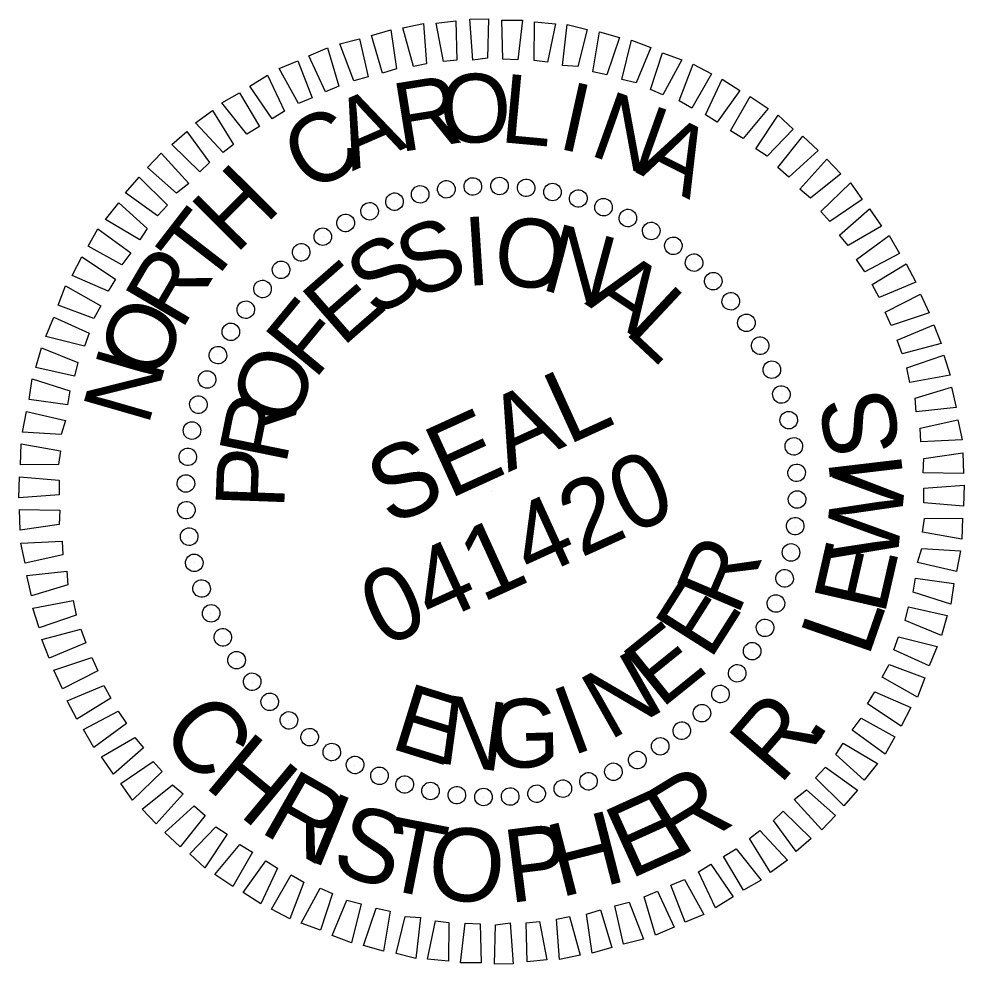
# Model space of a CAD drawing. Extents: x 2245059 to 2247045, y 661437 to 663204.
# Drawn here: x 2246903.7 to 2246981.3, y 663126.9 to 663204.4 of the extents above; entities that cross this region are included whole.
import ezdxf

# ---------------------------------------------------------------- set-up
doc = ezdxf.new("R2010")
doc.units = 0
doc.layers.add('Sheet PE Seal Cell', color=7, linetype='Continuous')

msp = doc.modelspace()

# ---------------------------------------------------------------- linework, layer by layer
at = {"layer": 'Sheet PE Seal Cell'}
for p, q in [((2246940.978, 663190.735), (2246940.978, 663190.735)), ((2246943.171, 663190.745), (2246943.171, 663190.745)), ((2246945.36, 663190.644), (2246945.36, 663190.644)), ((2246936.679, 663190.04), (2246936.679, 663190.04)), ((2246938.777, 663190.501), (2246938.777, 663190.501)), ((2246947.516, 663190.253), (2246947.516, 663190.253)), ((2246934.577, 663189.467), (2246934.577, 663189.467)), ((2246949.669, 663189.75), (2246949.669, 663189.75)), ((2246932.513, 663188.691), (2246932.513, 663188.691)), ((2246951.701, 663189.028), (2246951.701, 663189.028)), ((2246930.532, 663187.734), (2246930.532, 663187.734)), ((2246953.75, 663188.149), (2246953.75, 663188.149)), ((2246955.613, 663187.074), (2246955.613, 663187.074)), ((2246928.7, 663186.569), (2246928.7, 663186.569)), ((2246926.864, 663185.293), (2246926.864, 663185.293)), ((2246957.448, 663185.822), (2246957.448, 663185.822)), ((2246959.166, 663184.462), (2246959.166, 663184.462)), ((2246925.202, 663183.876), (2246925.202, 663183.876)), ((2246960.724, 663182.974), (2246960.724, 663182.974)), ((2246923.714, 663182.319), (2246923.714, 663182.319)), ((2246962.14, 663181.312), (2246962.14, 663181.312)), ((2246922.354, 663180.6), (2246922.354, 663180.6)), ((2246963.417, 663179.476), (2246963.417, 663179.476)), ((2246921.102, 663178.766), (2246921.102, 663178.766)), ((2246964.581, 663177.644), (2246964.581, 663177.644)), ((2246920.028, 663176.903), (2246920.028, 663176.903)), ((2246965.539, 663175.663), (2246965.539, 663175.663)), ((2246919.148, 663174.854), (2246919.148, 663174.854)), ((2246966.315, 663173.599), (2246966.315, 663173.599)), ((2246918.426, 663172.821), (2246918.426, 663172.821)), ((2246966.888, 663171.497), (2246966.888, 663171.497)), ((2246917.923, 663170.669), (2246917.923, 663170.669)), ((2246967.349, 663169.399), (2246967.349, 663169.399)), ((2246917.532, 663168.513), (2246917.532, 663168.513)), ((2246967.583, 663167.198), (2246967.583, 663167.198)), ((2246917.431, 663166.323), (2246917.431, 663166.323)), ((2246942.512, 663165.664), (2246942.512, 663165.664)), ((2246967.593, 663165.005), (2246967.593, 663165.005)), ((2246917.441, 663164.13), (2246917.441, 663164.13)), ((2246967.492, 663162.816), (2246967.492, 663162.816)), ((2246917.675, 663161.929), (2246917.675, 663161.929)), ((2246967.101, 663160.66), (2246967.101, 663160.66)), ((2246918.136, 663159.832), (2246918.136, 663159.832)), ((2246966.598, 663158.507), (2246966.598, 663158.507)), ((2246918.709, 663157.73), (2246918.709, 663157.73)), ((2246965.876, 663156.475), (2246965.876, 663156.475)), ((2246919.485, 663155.666), (2246919.485, 663155.666)), ((2246964.996, 663154.426), (2246964.996, 663154.426)), ((2246920.443, 663153.685), (2246920.443, 663153.685)), ((2246921.607, 663151.853), (2246921.607, 663151.853)), ((2246963.922, 663152.563), (2246963.922, 663152.563)), ((2246962.67, 663150.728), (2246962.67, 663150.728)), ((2246922.883, 663150.016), (2246922.883, 663150.016)), ((2246961.31, 663149.01), (2246961.31, 663149.01)), ((2246924.3, 663148.354), (2246924.3, 663148.354)), ((2246959.822, 663147.453), (2246959.822, 663147.453)), ((2246925.857, 663146.866), (2246925.857, 663146.866)), ((2246958.16, 663146.036), (2246958.16, 663146.036)), ((2246927.576, 663145.506), (2246927.576, 663145.506)), ((2246929.41, 663144.254), (2246929.41, 663144.254)), ((2246956.324, 663144.76), (2246956.324, 663144.76)), ((2246954.492, 663143.595), (2246954.492, 663143.595)), ((2246931.273, 663143.18), (2246931.273, 663143.18)), ((2246952.51, 663142.637), (2246952.51, 663142.637)), ((2246933.323, 663142.301), (2246933.323, 663142.301)), ((2246950.446, 663141.862), (2246950.446, 663141.862)), ((2246935.355, 663141.578), (2246935.355, 663141.578)), ((2246937.507, 663141.076), (2246937.507, 663141.076)), ((2246948.345, 663141.288), (2246948.345, 663141.288)), ((2246939.664, 663140.684), (2246939.664, 663140.684)), ((2246941.853, 663140.583), (2246941.853, 663140.583)), ((2246944.046, 663140.593), (2246944.046, 663140.593)), ((2246946.247, 663140.827), (2246946.247, 663140.827))]:
    msp.add_line(p, q, dxfattribs=at)
for points in [[(2246936.119, 663200.554), (2246935.226, 663203.719), (2246936.939, 663204.06), (2246937.178, 663200.762)], [(2246938.572, 663200.958), (2246937.969, 663204.09), (2246939.587, 663204.278), (2246939.673, 663201.075)], [(2246940.993, 663201.072), (2246940.733, 663204.415), (2246942.256, 663204.45), (2246942.185, 663201.23)], [(2246943.434, 663201.14), (2246943.349, 663204.343), (2246945.049, 663204.349), (2246944.663, 663201.096)], [(2246946.004, 663201.048), (2246946.051, 663204.201), (2246947.768, 663204.049), (2246947.117, 663200.896)], [(2246948.338, 663200.628), (2246948.728, 663203.992), (2246950.347, 663203.576), (2246949.588, 663200.538)], [(2246933.57, 663199.997), (2246932.653, 663203.096), (2246934.258, 663203.553), (2246934.724, 663200.358)], [(2246950.826, 663200.113), (2246951.369, 663203.382), (2246953.008, 663202.921), (2246951.981, 663199.87)], [(2246931.221, 663199.366), (2246930.055, 663202.407), (2246931.681, 663202.818), (2246932.395, 663199.682)], [(2246953.197, 663199.49), (2246953.985, 663202.706), (2246955.574, 663202.112), (2246954.373, 663199.202)], [(2246928.883, 663198.466), (2246927.536, 663201.423), (2246929.058, 663202.062), (2246929.996, 663198.918)], [(2246955.561, 663198.644), (2246956.543, 663201.674), (2246958.133, 663201.08), (2246956.575, 663198.227)], [(2246926.679, 663197.516), (2246925.104, 663200.37), (2246926.626, 663201.009), (2246927.791, 663197.968)], [(2246957.9, 663197.732), (2246959.06, 663200.733), (2246960.575, 663199.94), (2246958.952, 663197.112)], [(2246924.507, 663196.252), (2246922.68, 663198.936), (2246924.144, 663199.823), (2246925.537, 663196.886)], [(2246960.073, 663196.579), (2246961.432, 663199.506), (2246962.898, 663198.581), (2246961.013, 663195.964)], [(2246922.448, 663194.984), (2246920.393, 663197.564), (2246921.832, 663198.385), (2246923.478, 663195.618)], [(2246962.107, 663195.253), (2246963.73, 663198.081), (2246965.217, 663197.11), (2246963.158, 663194.633)], [(2246920.492, 663193.488), (2246918.23, 663195.919), (2246919.632, 663196.943), (2246921.344, 663194.151)], [(2246964.202, 663193.79), (2246966.024, 663196.544), (2246967.258, 663195.403), (2246965.142, 663193.175)], [(2246918.578, 663191.902), (2246916.287, 663194.155), (2246917.511, 663195.207), (2246919.388, 663192.656)], [(2246966.003, 663192.248), (2246968.066, 663194.837), (2246969.321, 663193.65), (2246966.914, 663191.455)], [(2246916.68, 663190.158), (2246914.294, 663192.258), (2246915.411, 663193.426), (2246917.693, 663190.949)], [(2246967.797, 663190.483), (2246970.033, 663192.931), (2246971.176, 663191.748), (2246968.687, 663189.735)], [(2246915.113, 663188.29), (2246912.496, 663190.175), (2246913.616, 663191.454), (2246915.928, 663189.156)], [(2246969.52, 663188.631), (2246971.955, 663191.004), (2246972.912, 663189.627), (2246970.274, 663187.821)], [(2246913.654, 663186.307), (2246910.851, 663187.996), (2246911.93, 663189.367), (2246914.27, 663187.246)], [(2246971.061, 663186.696), (2246973.533, 663188.866), (2246974.511, 663187.444), (2246971.769, 663185.865)], [(2246912.171, 663184.257), (2246909.43, 663185.81), (2246910.219, 663187.214), (2246912.923, 663185.259)], [(2246972.466, 663184.698), (2246975.133, 663186.683), (2246975.974, 663185.198), (2246973.145, 663183.689)], [(2246911.064, 663182.104), (2246908.112, 663183.396), (2246908.905, 663184.912), (2246911.659, 663183.089)], [(2246973.734, 663182.639), (2246976.525, 663184.351), (2246977.321, 663182.845), (2246974.322, 663181.588)], [(2246909.887, 663179.864), (2246906.972, 663180.954), (2246907.567, 663182.543), (2246910.461, 663180.895)], [(2246974.816, 663180.385), (2246977.711, 663181.869), (2246978.416, 663180.322), (2246975.314, 663179.293)], [(2246909.111, 663177.588), (2246905.94, 663178.396), (2246906.601, 663179.96), (2246909.507, 663178.647)], [(2246975.807, 663178.089), (2246978.806, 663179.346), (2246979.399, 663177.803), (2246976.214, 663176.956)], [(2246908.306, 663175.133), (2246905.132, 663175.829), (2246905.594, 663177.468), (2246908.57, 663176.242)], [(2246976.575, 663175.801), (2246979.611, 663176.855), (2246980.134, 663175.225), (2246976.845, 663174.606)], [(2246907.729, 663172.782), (2246904.567, 663173.209), (2246904.83, 663174.923), (2246907.927, 663173.916)], [(2246977.268, 663173.315), (2246980.255, 663174.237), (2246980.641, 663172.545), (2246977.34, 663172.194)], [(2246907.193, 663170.34), (2246904.024, 663170.544), (2246904.353, 663172.233), (2246907.548, 663171.491)], [(2246977.672, 663170.862), (2246980.762, 663171.556), (2246981.128, 663169.909), (2246977.743, 663169.74)], [(2246906.993, 663167.886), (2246903.881, 663167.842), (2246903.921, 663169.563), (2246907.145, 663168.999)], [(2246977.985, 663168.367), (2246981.179, 663168.833), (2246981.23, 663167.153), (2246977.92, 663167.183)], [(2246907.037, 663165.378), (2246903.739, 663165.139), (2246903.779, 663166.861), (2246907.036, 663166.587)], [(2246977.987, 663165.95), (2246981.285, 663166.189), (2246981.245, 663164.468), (2246977.988, 663164.742)], [(2246907.039, 663162.962), (2246903.845, 663162.495), (2246903.794, 663164.175), (2246907.104, 663164.145)], [(2246978.031, 663163.443), (2246981.142, 663163.487), (2246981.103, 663161.765), (2246977.879, 663162.329)], [(2246907.352, 663160.467), (2246904.261, 663159.773), (2246903.896, 663161.42), (2246907.28, 663161.588)], [(2246977.83, 663160.988), (2246981, 663160.785), (2246980.671, 663159.096), (2246977.475, 663159.838)], [(2246907.755, 663158.013), (2246904.769, 663157.092), (2246904.382, 663158.784), (2246907.684, 663159.135)], [(2246977.295, 663158.547), (2246980.456, 663158.119), (2246980.193, 663156.406), (2246977.097, 663157.413)], [(2246908.449, 663155.527), (2246905.413, 663154.473), (2246904.89, 663156.103), (2246908.179, 663156.723)], [(2246976.717, 663156.196), (2246979.892, 663155.499), (2246979.43, 663153.86), (2246976.454, 663155.086)], [(2246909.217, 663153.239), (2246906.218, 663151.983), (2246905.624, 663153.526), (2246908.81, 663154.373)], [(2246975.913, 663153.741), (2246979.083, 663152.933), (2246978.423, 663151.368), (2246975.517, 663152.681)], [(2246910.208, 663150.944), (2246907.312, 663149.46), (2246906.608, 663151.007), (2246909.71, 663152.036)], [(2246975.137, 663151.464), (2246978.051, 663150.375), (2246977.457, 663148.785), (2246974.563, 663150.433)], [(2246911.29, 663148.69), (2246908.498, 663146.978), (2246907.702, 663148.483), (2246910.701, 663149.74)], [(2246973.96, 663149.225), (2246976.911, 663147.932), (2246976.118, 663146.417), (2246973.365, 663148.239)], [(2246912.558, 663146.63), (2246909.891, 663144.645), (2246909.049, 663146.13), (2246911.878, 663147.639)], [(2246972.853, 663147.072), (2246975.594, 663145.518), (2246974.805, 663144.115), (2246972.101, 663146.07)], [(2246913.963, 663144.633), (2246911.49, 663142.462), (2246910.512, 663143.885), (2246913.254, 663145.464)], [(2246971.369, 663145.022), (2246974.172, 663143.332), (2246973.094, 663141.961), (2246970.754, 663144.082)], [(2246915.504, 663142.698), (2246913.069, 663140.324), (2246912.112, 663141.701), (2246914.75, 663143.508)], [(2246969.91, 663143.039), (2246972.527, 663141.154), (2246971.407, 663139.874), (2246969.096, 663142.173)], [(2246917.227, 663140.845), (2246914.991, 663138.398), (2246913.847, 663139.58), (2246916.337, 663141.594)], [(2246968.344, 663141.171), (2246970.729, 663139.071), (2246969.613, 663137.903), (2246967.331, 663140.379)], [(2246919.02, 663139.08), (2246916.958, 663136.492), (2246915.703, 663137.678), (2246918.109, 663139.874)], [(2246966.446, 663139.427), (2246968.737, 663137.174), (2246967.513, 663136.122), (2246965.636, 663138.673)], [(2246920.822, 663137.538), (2246919, 663134.785), (2246917.765, 663135.926), (2246919.882, 663138.154)], [(2246964.532, 663137.84), (2246966.793, 663135.409), (2246965.392, 663134.386), (2246963.68, 663137.177)], [(2246922.917, 663136.075), (2246921.294, 663133.248), (2246919.807, 663134.219), (2246921.866, 663136.695)], [(2246962.576, 663136.345), (2246964.631, 663133.764), (2246963.191, 663132.944), (2246961.546, 663135.71)], [(2246924.95, 663134.749), (2246923.592, 663131.822), (2246922.126, 663132.748), (2246924.01, 663135.365)], [(2246960.516, 663135.076), (2246962.344, 663132.392), (2246960.88, 663131.506), (2246959.486, 663134.442)], [(2246927.124, 663133.597), (2246925.964, 663130.595), (2246924.449, 663131.388), (2246926.072, 663134.216)], [(2246958.345, 663133.812), (2246959.92, 663130.958), (2246958.398, 663130.32), (2246957.232, 663133.36)], [(2246929.463, 663132.684), (2246928.481, 663129.654), (2246926.891, 663130.249), (2246928.448, 663133.101)], [(2246956.14, 663132.863), (2246957.488, 663129.905), (2246955.966, 663129.266), (2246955.028, 663132.41)], [(2246931.826, 663131.838), (2246931.039, 663128.622), (2246929.449, 663129.217), (2246930.651, 663132.127)], [(2246953.803, 663131.962), (2246954.969, 663128.922), (2246953.343, 663128.511), (2246952.628, 663131.647)], [(2246934.198, 663131.216), (2246933.655, 663127.946), (2246932.016, 663128.408), (2246933.043, 663131.459)], [(2246951.453, 663131.331), (2246952.371, 663128.233), (2246950.766, 663127.776), (2246950.299, 663130.97)], [(2246936.685, 663130.701), (2246936.295, 663127.336), (2246934.677, 663127.753), (2246935.436, 663130.791)], [(2246939.02, 663130.281), (2246938.973, 663127.128), (2246937.255, 663127.279), (2246937.906, 663130.433)], [(2246941.589, 663130.188), (2246941.675, 663126.985), (2246939.974, 663126.98), (2246940.36, 663130.232)], [(2246944.031, 663130.257), (2246944.29, 663126.913), (2246942.768, 663126.879), (2246942.839, 663130.098)], [(2246946.451, 663130.371), (2246947.054, 663127.239), (2246945.437, 663127.051), (2246945.351, 663130.254)], [(2246948.905, 663130.774), (2246949.798, 663127.61), (2246948.085, 663127.269), (2246947.846, 663130.566)]]:
    msp.add_lwpolyline(points, close=True, dxfattribs=at)
for centre, major_axis in [((2246940.982, 663190.698), (-0.044, 0.719)), ((2246943.169, 663190.736), (0.019, 0.72)), ((2246936.658, 663190.052), (-0.168, 0.7)), ((2246938.806, 663190.469), (-0.106, 0.712)), ((2246945.352, 663190.583), (0.082, 0.715)), ((2246947.513, 663190.241), (0.144, 0.706)), ((2246934.555, 663189.449), (-0.228, 0.683)), ((2246949.636, 663189.711), (0.205, 0.69)), ((2246932.512, 663188.664), (-0.287, 0.66)), ((2246951.705, 663188.999), (0.264, 0.67)), ((2246930.545, 663187.705), (-0.344, 0.633)), ((2246953.703, 663188.109), (0.321, 0.644)), ((2246955.617, 663187.048), (0.376, 0.614)), ((2246928.67, 663186.579), (-0.397, 0.6)), ((2246926.9, 663185.293), (-0.448, 0.563)), ((2246957.431, 663185.824), (0.428, 0.579)), ((2246959.131, 663184.447), (0.477, 0.539)), ((2246925.249, 663183.857), (-0.496, 0.522)), ((2246960.705, 663182.928), (0.522, 0.496)), ((2246923.729, 663182.283), (-0.539, 0.477)), ((2246962.14, 663181.276), (0.563, 0.448)), ((2246922.352, 663180.583), (-0.579, 0.428)), ((2246963.426, 663179.506), (0.6, 0.397)), ((2246921.128, 663178.769), (-0.614, 0.376)), ((2246964.553, 663177.631), (0.633, 0.344)), ((2246920.067, 663176.856), (-0.644, 0.321)), ((2246965.512, 663175.664), (0.66, 0.287)), ((2246919.177, 663174.857), (-0.67, 0.264)), ((2246966.296, 663173.621), (0.683, 0.228)), ((2246918.465, 663172.788), (-0.69, 0.205)), ((2246966.899, 663171.518), (0.7, 0.168)), ((2246917.936, 663170.665), (-0.706, 0.144)), ((2246967.316, 663169.37), (0.712, 0.106)), ((2246917.593, 663168.504), (-0.715, 0.082)), ((2246967.545, 663167.194), (0.719, 0.044)), ((2246917.44, 663166.322), (-0.72, 0.019)), ((2246967.583, 663165.007), (0.72, -0.019)), ((2246917.479, 663164.134), (-0.719, -0.044)), ((2246967.431, 663162.824), (0.715, -0.082)), ((2246917.707, 663161.958), (-0.712, -0.106)), ((2246967.088, 663160.663), (0.706, -0.144)), ((2246918.125, 663159.81), (-0.7, -0.168)), ((2246966.559, 663158.54), (0.69, -0.205)), ((2246918.728, 663157.707), (-0.683, -0.228)), ((2246965.846, 663156.472), (0.67, -0.264)), ((2246919.512, 663155.664), (-0.66, -0.287)), ((2246964.956, 663154.473), (0.644, -0.321)), ((2246920.471, 663153.698), (-0.633, -0.344)), ((2246963.896, 663152.559), (0.614, -0.376)), ((2246921.597, 663151.822), (-0.6, -0.397)), ((2246962.672, 663150.745), (0.579, -0.428)), ((2246922.883, 663150.052), (-0.563, -0.448)), ((2246961.295, 663149.045), (0.539, -0.477)), ((2246924.319, 663148.401), (-0.522, -0.496)), ((2246959.775, 663147.471), (0.496, -0.522)), ((2246925.893, 663146.881), (-0.477, -0.539)), ((2246958.124, 663146.036), (0.448, -0.563)), ((2246927.593, 663145.504), (-0.428, -0.579)), ((2246929.407, 663144.281), (-0.376, -0.614)), ((2246956.354, 663144.75), (0.397, -0.6)), ((2246954.478, 663143.623), (0.344, -0.633)), ((2246931.32, 663143.22), (-0.321, -0.644)), ((2246952.512, 663142.664), (0.287, -0.66)), ((2246933.319, 663142.33), (-0.264, -0.67)), ((2246950.469, 663141.88), (0.228, -0.683)), ((2246935.388, 663141.617), (-0.205, -0.69)), ((2246937.511, 663141.088), (-0.144, -0.706)), ((2246948.366, 663141.277), (0.168, -0.7)), ((2246939.672, 663140.746), (-0.082, -0.715)), ((2246941.854, 663140.593), (-0.019, -0.72)), ((2246944.042, 663140.631), (0.044, -0.719)), ((2246946.218, 663140.86), (0.106, -0.712))]:
    msp.add_ellipse(centre, major_axis=major_axis, ratio=0.999708, dxfattribs=at)

# ---------------------------------------------------------------- texts
for s, height, rotation, p in [('O', 5.638, 1.91911, (2246938.351, 663194.209)), ('R', 5.638, 9.11904, (2246934.992, 663193.502)), ('L', 5.638, 354.71882, (2246943.122, 663194.35)), ('I', 5.638, 347.51808, (2246947.803, 663193.845)), ('N', 5.639, 340.31685, (2246950.402, 663193.326)), ('A', 5.638, 23.51826, (2246931.087, 663191.942)), ('C', 5.638, 30.71781, (2246927.617, 663190.032)), ('A', 5.639, 333.1151, (2246954.31, 663191.865)), ('H', 5.638, 45.11742, (2246921.53, 663185.06)), ('T', 5.638, 52.31772, (2246919.257, 663182.211)), ('S', 5.638, 22.39834, (2246936.232, 663181.375)), ('I', 5.638, 3.68755, (2246940.435, 663182.521)), ('O', 5.638, 354.33143, (2246942.545, 663182.713)), ('N', 5.638, 344.97455, (2246946.423, 663182.282)), ('S', 5.638, 31.75355, (2246932.977, 663179.836)), ('R', 5.639, 59.51845, (2246917.075, 663178.799)), ('E', 5.638, 41.10901, (2246930.273, 663177.45)), ('A', 5.639, 326.25821, (2246950.095, 663181.098)), ('L', 5.639, 316.89879, (2246953.3, 663178.767)), ('F', 5.638, 50.46498, (2246927.983, 663174.758)), ('O', 5.639, 66.71968, (2246915.221, 663174.548)), ('N', 5.639, 73.92144, (2246914.331, 663170.955)), ('O', 5.639, 69.17918, (2246926.203, 663170.706)), ('SEAL', 5.9982, 24.49794, (2246934.153, 663162.788)), ('S', 5.998, 100.55241, (2246976.159, 663169.066)), ('R', 5.639, 78.53759, (2246925.627, 663167.75)), ('P', 5.639, 87.89683, (2246925.498, 663164.175)), ('041420', 5.9982, 24.49794, (2246933.603, 663152.804)), ('I', 5.998, 96.75046, (2246976.31, 663166.827)), ('W', 5.998, 84.21639, (2246975.757, 663159.465)), ('R', 5.639, 66.97935, (2246962.703, 663155.359)), ('E', 5.998, 77.10705, (2246974.734, 663155.398)), ('E', 5.638, 57.62203, (2246960.447, 663151.748)), ('L', 5.998, 70.83229, (2246973.419, 663151.937)), ('E', 5.638, 38.9097, (2246956.432, 663147.776)), ('N', 5.638, 29.55433, (2246952.177, 663145.178)), ('E', 5.638, 342.77483, (2246934.078, 663144.623)), ('I', 5.638, 20.19914, (2246949.066, 663143.925)), ('N', 5.638, 352.1319, (2246937.927, 663143.41)), ('G', 5.638, 1.48818, (2246942.318, 663142.938)), ('R', 5.998, 49.11789, (2246966.147, 663141.477)), ('C', 5.998, 310.69992, (2246915.125, 663145.825)), ('.', 5.998, 56.59815, (2246969.095, 663144.759)), ('H', 5.998, 320.28207, (2246918.809, 663141.543)), ('R', 5.998, 330.26605, (2246923.35, 663137.798)), ('R', 5.998, 31.43728, (2246957.684, 663135.441)), ('E', 5.998, 24.32794, (2246953.827, 663133.795)), ('I', 5.998, 337.74631, (2246927.141, 663135.541)), ('S', 5.998, 341.54826, (2246929.172, 663134.588)), ('T', 5.998, 348.87397, (2246933.244, 663133.141)), ('H', 5.998, 14.34395, (2246948.131, 663132.316)), ('O', 5.998, 355.67421, (2246937.16, 663132.272)), ('P', 5.998, 7.23461, (2246943.96, 663131.877))]:
    msp.add_text(s, height=height, rotation=rotation, dxfattribs=at).set_placement(p)

doc.saveas('drawing.dxf')
